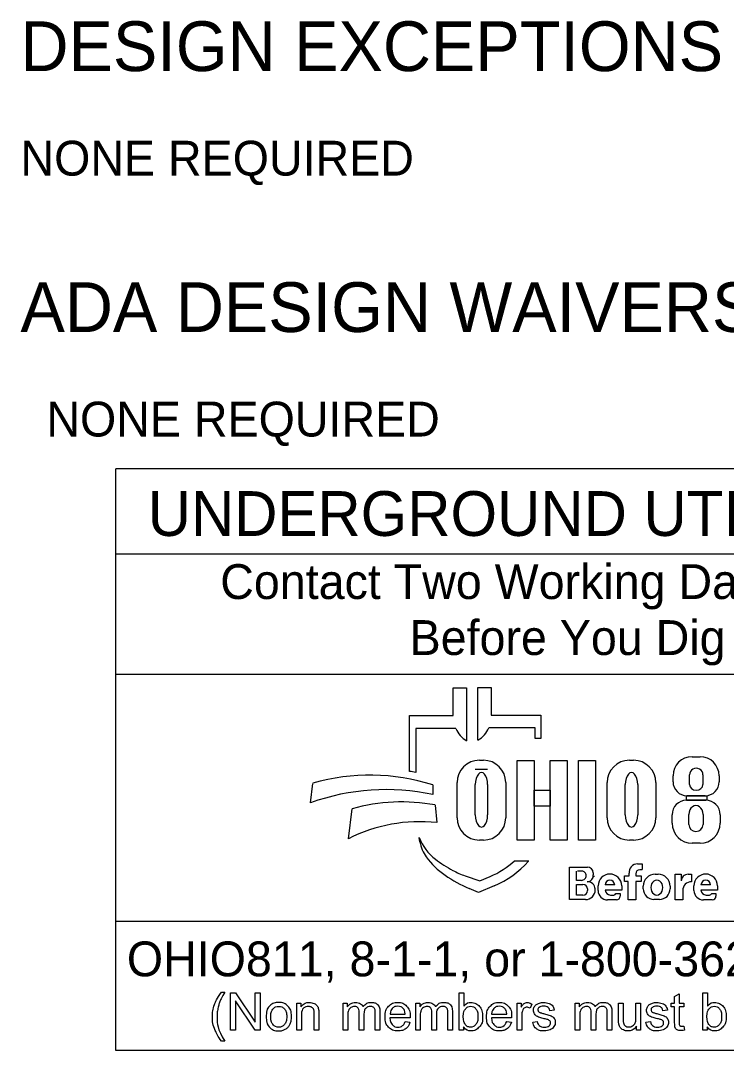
# Model space of a CAD drawing. Extents: x 0 to 34, y 0 to 22.
# Drawn here: x 1.995 to 4.831, y 2.143 to 6.282 of the extents above; entities that cross this region are included whole.
import ezdxf

# ---------------------------------------------------------------- set-up
doc = ezdxf.new("R2010")
doc.units = 0
doc.layers.add('SH_Data', color=7, linetype='Continuous')
doc.layers.add('SH_Text', color=7, linetype='Continuous')

msp = doc.modelspace()

# ---------------------------------------------------------------- linework, layer by layer
at = {"layer": 'SH_Data'}
for p, q in [((2.3775, 2.1428), (2.3775, 4.4803)), ((6.6275, 4.4803), (2.3775, 4.4803)), ((2.3775, 4.1387), (6.6275, 4.1387)), ((2.3775, 3.6553), (6.6275, 3.6553)), ((6.6275, 2.6607), (2.3775, 2.6607)), ((6.6275, 2.1428), (2.3775, 2.1428))]:
    msp.add_line(p, q, dxfattribs=at)
at = {"layer": 'SH_Text'}
for p, q in [((3.8329, 3.39), (3.8329, 3.6021)), ((3.8329, 3.6021), (3.8865, 3.6021)), ((3.8865, 3.6021), (3.8865, 3.4906)), ((3.7335, 3.4883), (3.7335, 3.5998)), ((3.7335, 3.5998), (3.7872, 3.5998)), ((3.7872, 3.5998), (3.7872, 3.3877)), ((3.5576, 3.2644), (3.5576, 3.4883)), ((3.5576, 3.4883), (3.7335, 3.4883)), ((3.8865, 3.4906), (4.0857, 3.4906)), ((4.0857, 3.4906), (4.0857, 3.3968)), ((3.5828, 3.4369), (3.5828, 3.26)), ((3.7439, 3.4369), (3.5828, 3.4369)), ((4.0625, 3.4392), (3.8761, 3.4392)), ((4.0625, 3.3968), (4.0625, 3.4392)), ((4.0857, 3.3968), (4.0625, 3.3968)), ((4.6931, 3.3231), (4.7258, 3.3231)), ((3.8718, 3.2721), (3.822, 3.2721)), ((3.8385, 3.3091), (3.8551, 3.3091)), ((4.4416, 3.3091), (4.4581, 3.3091)), ((4.6168, 3.2225), (4.6168, 3.2468)), ((4.683, 3.2111), (4.683, 3.2504)), ((4.7371, 3.2504), (4.7371, 3.2111)), ((4.8022, 3.2468), (4.8022, 3.2225)), ((3.1602, 3.1381), (3.1696, 3.2162)), ((3.6509, 3.2097), (3.6509, 3.1709)), ((3.7491, 3.0776), (3.7491, 3.2196)), ((3.822, 3.089), (3.822, 3.2114)), ((3.8718, 3.2114), (3.8718, 3.089)), ((3.9445, 3.2196), (3.9445, 3.0776)), ((4.3521, 3.0776), (4.3521, 3.2196)), ((4.425, 3.089), (4.425, 3.2114)), ((4.4748, 3.2114), (4.4748, 3.089)), ((4.5476, 3.2196), (4.5476, 3.0776)), ((4.671, 3.1482), (4.7483, 3.1482)), ((4.7462, 3.1665), (4.6728, 3.1665)), ((3.312, 2.9936), (3.3267, 3.1137)), ((3.6608, 3.1291), (3.6671, 3.0582)), ((4.6131, 3.0563), (4.6131, 3.0903)), ((4.6806, 3.0503), (4.6806, 3.0912)), ((4.7374, 3.0912), (4.7374, 3.0503)), ((4.8062, 3.0903), (4.8062, 3.0563)), ((3.5997, 2.9807), (3.5967, 2.9986)), ((3.8551, 2.9882), (3.8385, 2.9882)), ((4.4581, 2.9882), (4.4416, 2.9882)), ((4.7252, 2.9753), (4.6941, 2.9753)), ((3.98, 2.9048), (4.0375, 2.9048)), ((4.2013, 2.749), (4.2013, 2.8798)), ((4.2013, 2.8798), (4.2725, 2.8798)), ((4.2293, 2.8263), (4.2293, 2.8632)), ((4.2545, 2.8632), (4.2332, 2.8632)), ((4.4739, 2.8926), (4.4934, 2.8926)), ((4.4934, 2.8691), (4.4832, 2.8691)), ((4.4934, 2.8926), (4.4934, 2.8696)), ((3.7816, 2.8444), (3.841, 2.8239)), ((3.841, 2.8239), (3.8821, 2.8417)), ((4.2487, 2.8263), (4.2293, 2.8263)), ((4.2963, 2.856), (4.2963, 2.8481)), ((4.4213, 2.8212), (4.4213, 2.8442)), ((4.4213, 2.8442), (4.4406, 2.8442)), ((4.4362, 2.8212), (4.4213, 2.8212)), ((4.4362, 2.7478), (4.4362, 2.8212)), ((4.4406, 2.8442), (4.4406, 2.8546)), ((4.4667, 2.8526), (4.4667, 2.8442)), ((4.4667, 2.8442), (4.4883, 2.8442)), ((4.4883, 2.8212), (4.4667, 2.8212)), ((4.4667, 2.8212), (4.4667, 2.7478)), ((4.4883, 2.8442), (4.4883, 2.8212)), ((4.5451, 2.8508), (4.5573, 2.8508)), ((4.6254, 2.7478), (4.6254, 2.8505)), ((4.6254, 2.8505), (4.6499, 2.8505)), ((4.6499, 2.8505), (4.6499, 2.8237)), ((4.6772, 2.8505), (4.691, 2.8505)), ((4.691, 2.8505), (4.691, 2.8209)), ((3.835, 2.7769), (3.7976, 2.7934)), ((3.8983, 2.8044), (3.835, 2.7769)), ((4.2293, 2.7669), (4.2293, 2.8097)), ((4.2293, 2.8097), (4.2548, 2.8097)), ((4.2729, 2.7916), (4.2729, 2.7853)), ((4.3043, 2.7887), (4.3043, 2.7884)), ((4.3159, 2.7858), (4.3159, 2.8042)), ((4.3824, 2.8082), (4.3439, 2.8082)), ((4.4104, 2.7866), (4.344, 2.7866)), ((4.4104, 2.8042), (4.4104, 2.7866)), ((4.4973, 2.7922), (4.4973, 2.8029)), ((4.6051, 2.8029), (4.6051, 2.7922)), ((4.6559, 2.786), (4.6559, 2.7478)), ((4.7008, 2.7858), (4.7008, 2.8042)), ((4.7674, 2.8082), (4.7288, 2.8082)), ((4.7953, 2.7866), (4.7289, 2.7866)), ((4.7953, 2.8042), (4.7953, 2.7866)), ((4.265, 2.749), (4.2013, 2.749)), ((4.2546, 2.7669), (4.2293, 2.7669)), ((4.3892, 2.7478), (4.3538, 2.7478)), ((4.3649, 2.7673), (4.379, 2.7673)), ((4.3876, 2.7729), (4.4045, 2.7729)), ((4.4045, 2.7729), (4.4045, 2.7631)), ((4.4667, 2.7478), (4.4362, 2.7478)), ((4.5623, 2.7494), (4.5401, 2.7494)), ((4.6559, 2.7478), (4.6254, 2.7478)), ((4.7742, 2.7478), (4.7388, 2.7478)), ((4.7498, 2.7673), (4.7639, 2.7673)), ((4.7725, 2.7729), (4.7894, 2.7729)), ((4.7894, 2.7729), (4.7894, 2.7631))]:
    msp.add_line(p, q, dxfattribs=at)
for points in [[(3.991, 3.3081), (4.0589, 3.3081), (4.0589, 2.9881), (3.991, 2.9881)], [(4.1231, 3.3081), (4.1911, 3.3081), (4.1911, 2.9881), (4.1231, 2.9881)], [(4.2364, 3.3081), (4.3052, 3.3081), (4.3052, 2.9881), (4.2364, 2.9881)], [(4.0589, 3.1882), (4.1231, 3.1882), (4.1231, 3.1242), (4.0589, 3.1242)], [(4.6706, 3.1665), (4.7523, 3.1665), (4.7523, 3.1481), (4.6706, 3.1481)]]:
    msp.add_lwpolyline(points, close=True, dxfattribs=at)
for points in [[(2.8021, 2.3766), (2.8153, 2.3766)], [(2.8389, 2.2239), (2.8389, 2.3741), (2.8592, 2.3741), (2.9382, 2.2561), (2.9382, 2.3741), (2.9572, 2.3741), (2.9572, 2.2239), (2.9369, 2.2239), (2.8579, 2.3419), (2.8579, 2.2239), (2.8389, 2.2239)], [(3.7743, 2.2239), (3.7573, 2.2239), (3.7573, 2.3741), (3.7757, 2.3741), (3.7757, 2.3206)], [(4.6233, 2.2558), (4.6233, 2.3185), (4.6097, 2.3185), (4.6097, 2.3328), (4.6233, 2.3328), (4.6233, 2.3597), (4.6417, 2.3708), (4.6417, 2.3328), (4.6601, 2.3328), (4.6601, 2.3185), (4.6417, 2.3185), (4.6417, 2.2547)], [(4.7534, 2.2239), (4.7363, 2.2239), (4.7363, 2.3741), (4.7548, 2.3741), (4.7548, 2.3206)], [(3.1048, 2.2239), (3.1048, 2.3328), (3.1214, 2.3328), (3.1214, 2.3173)], [(3.2912, 2.2239), (3.2912, 2.3328), (3.3077, 2.3328), (3.3077, 2.3174)], [(3.5826, 2.2239), (3.5826, 2.3328), (3.5991, 2.3328), (3.5991, 2.3174)], [(3.9904, 2.2239), (3.9904, 2.3328), (4.007, 2.3328), (4.007, 2.3163)], [(4.0495, 2.3293), (4.043, 2.3122)], [(4.2236, 2.2239), (4.2236, 2.3328), (4.2401, 2.3328), (4.2401, 2.3174)], [(4.3979, 2.2654), (4.3979, 2.3328), (4.4164, 2.3328), (4.4164, 2.2724)], [(4.4676, 2.2745), (4.4676, 2.3328), (4.4861, 2.3328), (4.4861, 2.2239), (4.4696, 2.2239)], [(3.1233, 2.2833), (3.1233, 2.2239), (3.1048, 2.2239)], [(3.1932, 2.2908), (3.1932, 2.2239), (3.1748, 2.2239), (3.1748, 2.2901)], [(3.3097, 2.2803), (3.3097, 2.2239), (3.2912, 2.2239)], [(3.3743, 2.2871), (3.3743, 2.2239), (3.3559, 2.2239), (3.3559, 2.2946)], [(3.4388, 2.2986), (3.4388, 2.2239), (3.4203, 2.2239), (3.4203, 2.2924)], [(3.4799, 2.2887), (3.5406, 2.2887)], [(3.601, 2.2803), (3.601, 2.2239), (3.5826, 2.2239)], [(3.6657, 2.2871), (3.6657, 2.2239), (3.6473, 2.2239), (3.6473, 2.2946)], [(3.7301, 2.2986), (3.7301, 2.2239), (3.7117, 2.2239), (3.7117, 2.2924)], [(3.8879, 2.2887), (3.9486, 2.2887)], [(4.0088, 2.2809), (4.0088, 2.2239), (3.9904, 2.2239)], [(4.1394, 2.3046), (4.1213, 2.3022)], [(4.242, 2.2803), (4.242, 2.2239), (4.2236, 2.2239)], [(4.3067, 2.2871), (4.3067, 2.2239), (4.2883, 2.2239), (4.2883, 2.2946)], [(4.3711, 2.2986), (4.3711, 2.2239), (4.3527, 2.2239), (4.3527, 2.2924)], [(4.594, 2.3046), (4.5759, 2.3022)], [(3.56, 2.2736), (3.4788, 2.2736)], [(3.5404, 2.2591), (3.5595, 2.2567)], [(3.7743, 2.2375), (3.7743, 2.2239)], [(3.968, 2.2736), (3.8868, 2.2736)], [(3.9484, 2.2591), (3.9675, 2.2567)], [(4.053, 2.2564), (4.0712, 2.2593)], [(4.4696, 2.2239), (4.4696, 2.24)], [(4.5076, 2.2564), (4.5258, 2.2593)], [(4.6601, 2.2404), (4.6628, 2.2241)], [(4.7534, 2.2375), (4.7534, 2.2239)], [(2.8153, 2.1798), (2.8021, 2.1798)]]:
    msp.add_lwpolyline(points, dxfattribs=at)
for centre, radius, start, end in [((3.8353, 3.4736), 0.0985, 201.9296, 240.7469), ((3.7847, 3.476), 0.0985, 299.2531, 338.0704), ((4.6931, 3.2468), 0.0763, 90, 180), ((4.7258, 3.2468), 0.0763, 0, 90), ((3.8385, 3.2196), 0.0895, 90, 180), ((3.8551, 3.2196), 0.0895, 0, 90), ((4.4416, 3.2196), 0.0895, 90, 180), ((4.4581, 3.2196), 0.0895, 0, 90), ((3.3997, 2.4302), 0.8191, 72.1402, 106.3144), ((3.4295, 2.4554), 0.8191, 79.2074, 81.0007), ((3.4628, 2.2991), 0.8919, 77.8238, 109.8274), ((4.6728, 3.2225), 0.056, 180, 270), ((4.7462, 3.2225), 0.056, 270, 0), ((4.671, 3.0903), 0.0579, 90, 180), ((4.7483, 3.0903), 0.0579, 0, 90), ((3.5267, 2.4094), 0.7322, 79.44, 105.8467), ((3.8385, 3.0776), 0.0895, 180, 270), ((3.8551, 3.0776), 0.0895, 270, 0), ((4.4416, 3.0776), 0.0895, 180, 270), ((4.4581, 3.0776), 0.0895, 270, 0), ((3.5987, 2.4262), 0.6357, 83.8248, 116.8021), ((4.6941, 3.0563), 0.081, 180, 270), ((4.7252, 3.0563), 0.081, 270, 0), ((3.7841, 3.0707), 0.2008, 201.0457, 232.5314), ((3.741, 3.0048), 0.1433, 189.6817, 216.0884), ((3.8747, 3.1022), 0.3088, 216.0884, 235.7167), ((3.9766, 3.3219), 0.5173, 232.5314, 241.794), ((3.7387, 3.1722), 0.3602, 293.4582, 312.0712), ((3.7387, 3.1722), 0.401, 293.4582, 317.8286), ((3.8914, 3.1631), 0.3371, 241.794, 250.9821), ((4.2505, 2.8463), 0.0169, 357.8325, 90), ((4.2725, 2.856), 0.0238, 0, 90), ((4.4739, 2.859), 0.0335, 90, 187.5187), ((4.4832, 2.8526), 0.0165, 90, 180), ((4.0412, 3.3465), 0.6044, 235.7167, 246.2325), ((4.2487, 2.845), 0.0187, 270, 2.0582), ((4.2721, 2.8453), 0.0243, 270, 6.6529), ((4.2722, 2.7889), 0.0321, 4.0748, 90), ((4.2827, 2.8438), 0.0175, 347.4023, 0), ((4.3631, 2.8042), 0.0473, 0, 180), ((4.3632, 2.8072), 0.0193, 2.9632, 177.0368), ((4.5451, 2.8029), 0.0478, 90, 180), ((4.5573, 2.8029), 0.0478, 0, 90), ((4.6768, 2.8237), 0.0269, 89.2449, 180), ((4.6908, 2.786), 0.0349, 89.6033, 180), ((4.7481, 2.8042), 0.0473, 0, 180), ((4.7481, 2.8072), 0.0193, 2.9632, 177.0368), ((4.2546, 2.7853), 0.0184, 270, 0), ((4.2548, 2.7916), 0.0181, 0, 90), ((4.265, 2.7884), 0.0393, 270, 0), ((4.2714, 2.7887), 0.033, 0, 11.7502), ((4.3538, 2.7858), 0.038, 180, 270), ((4.3649, 2.7883), 0.021, 184.827, 270), ((4.5401, 2.7922), 0.0428, 180, 270), ((4.5623, 2.7922), 0.0428, 270, 0), ((4.7388, 2.7858), 0.038, 180, 270), ((4.7498, 2.7883), 0.021, 184.827, 270), ((4.379, 2.7767), 0.00938, 270, 335.9979), ((4.3892, 2.7631), 0.0152, 270, 0), ((4.7639, 2.7767), 0.00938, 270, 335.9979), ((4.7742, 2.7631), 0.0152, 270, 0)]:
    msp.add_arc(centre, radius, start, end, dxfattribs=at)
for centre, major_axis, ratio, start_param, end_param in [((4.71, 3.2504), (0.0271, 0), 0.969373, 0, 3.141593), ((3.8469, 3.2114), (0, 0.0484), 0.514403, 4.712389, 7.853982), ((4.4499, 3.2114), (0, 0.0484), 0.514403, 4.712389, 7.853982), ((4.71, 3.2111), (0.0271, 0), 0.818453, 3.141593, 6.283185), ((4.709, 3.0912), (0, 0.0358), 0.794529, 4.712389, 7.853982), ((3.8469, 3.089), (0, 0.0484), 0.514403, 1.570796, 4.712389), ((4.4499, 3.089), (0, 0.0484), 0.514403, 1.570796, 4.712389), ((4.709, 3.0503), (0.0284, 0), 0.959837, 3.141593, 6.283185), ((4.5517, 2.7976), (0, 0.029), 0.832186, 4.712389, 7.853982), ((4.5517, 2.7976), (0, 0.0302), 0.797287, 1.570796, 4.712389)]:
    msp.add_ellipse(centre, major_axis=major_axis, ratio=ratio, start_param=start_param, end_param=end_param, dxfattribs=at)
for points in [[(2.8021, 2.1798), (2.7869, 2.199), (2.7763, 2.2248), (2.7657, 2.2506), (2.7657, 2.2783), (2.7657, 2.3026), (2.7736, 2.325), (2.7829, 2.3509), (2.8021, 2.3766)], [(2.8153, 2.3766), (2.8029, 2.3553), (2.7989, 2.3462), (2.7927, 2.332), (2.7891, 2.3167), (2.7847, 2.2975), (2.7847, 2.2782), (2.7847, 2.2289), (2.8153, 2.1798)], [(2.9814, 2.2783), (2.9814, 2.3085), (2.9981, 2.3231), (3.0122, 2.3352), (3.0323, 2.3352), (3.0547, 2.3352), (3.069, 2.3205), (3.0832, 2.3058), (3.0832, 2.2799), (3.0832, 2.2589), (3.0769, 2.2469), (3.0706, 2.2348), (3.0586, 2.2282), (3.0466, 2.2215), (3.0323, 2.2215), (3.0095, 2.2215), (2.9954, 2.2362), (2.9814, 2.2508), (2.9814, 2.2783)], [(3.0003, 2.2783), (3.0003, 2.2574), (3.0094, 2.247), (3.0185, 2.2366), (3.0323, 2.2366), (3.046, 2.2366), (3.0551, 2.2471), (3.0642, 2.2575), (3.0642, 2.279), (3.0642, 2.2991), (3.0551, 2.3095), (3.0459, 2.3199), (3.0323, 2.3199), (3.0185, 2.3199), (3.0094, 2.3096), (3.0003, 2.2992), (3.0003, 2.2783)], [(3.1214, 2.3173), (3.1334, 2.3352), (3.156, 2.3352), (3.1659, 2.3352), (3.1741, 2.3316), (3.1823, 2.3281), (3.1864, 2.3224), (3.1905, 2.3166), (3.1922, 2.3087), (3.1932, 2.3036), (3.1932, 2.2908)], [(3.1748, 2.2901), (3.1748, 2.3013), (3.1726, 2.3069), (3.1705, 2.3125), (3.165, 2.3158), (3.1595, 2.3191), (3.1521, 2.3191), (3.1404, 2.3191), (3.1318, 2.3117), (3.1233, 2.3042), (3.1233, 2.2833)], [(3.3077, 2.3174), (3.3128, 2.3254), (3.3214, 2.3303), (3.3299, 2.3352), (3.3407, 2.3352), (3.3528, 2.3352), (3.3606, 2.3301), (3.3683, 2.3251), (3.3715, 2.3161), (3.3844, 2.3352), (3.4051, 2.3352), (3.4213, 2.3352), (3.43, 2.3262), (3.4388, 2.3172), (3.4388, 2.2986)], [(3.3559, 2.2946), (3.3559, 2.3069), (3.3514, 2.313), (3.3469, 2.3191), (3.3366, 2.3191), (3.3288, 2.3191), (3.3222, 2.315), (3.3156, 2.311), (3.3126, 2.3031), (3.3097, 2.2952), (3.3097, 2.2803)], [(3.4203, 2.2924), (3.4203, 2.3035), (3.4185, 2.3083), (3.4168, 2.3132), (3.412, 2.3162), (3.4073, 2.3191), (3.401, 2.3191), (3.3895, 2.3191), (3.3819, 2.3115), (3.3743, 2.3039), (3.3743, 2.2871)], [(3.5595, 2.2567), (3.555, 2.24), (3.5428, 2.2307), (3.5306, 2.2215), (3.5117, 2.2215), (3.4878, 2.2215), (3.4738, 2.2362), (3.4598, 2.2509), (3.4598, 2.2774), (3.4598, 2.3049), (3.474, 2.32), (3.4881, 2.3352), (3.5106, 2.3352), (3.5324, 2.3352), (3.5463, 2.3203), (3.5601, 2.3055), (3.5601, 2.2785), (3.5601, 2.2769), (3.56, 2.2736)], [(3.5406, 2.2887), (3.5394, 2.3025), (3.5337, 2.3094), (3.5249, 2.3201), (3.5108, 2.3201), (3.4981, 2.3201), (3.4894, 2.3115), (3.4808, 2.303), (3.4799, 2.2887)], [(3.5991, 2.3174), (3.6042, 2.3254), (3.6127, 2.3303), (3.6212, 2.3352), (3.6321, 2.3352), (3.6442, 2.3352), (3.6519, 2.3301), (3.6597, 2.3251), (3.6628, 2.3161), (3.6758, 2.3352), (3.6965, 2.3352), (3.7127, 2.3352), (3.7214, 2.3262), (3.7301, 2.3172), (3.7301, 2.2986)], [(3.6473, 2.2946), (3.6473, 2.3069), (3.6428, 2.313), (3.6383, 2.3191), (3.628, 2.3191), (3.6202, 2.3191), (3.6136, 2.315), (3.607, 2.311), (3.604, 2.3031), (3.601, 2.2952), (3.601, 2.2803)], [(3.7117, 2.2924), (3.7117, 2.3035), (3.7099, 2.3083), (3.7081, 2.3132), (3.7034, 2.3162), (3.6987, 2.3191), (3.6923, 2.3191), (3.6809, 2.3191), (3.6733, 2.3115), (3.6657, 2.3039), (3.6657, 2.2871)], [(3.7741, 2.2792), (3.7741, 2.2596), (3.7794, 2.2509), (3.7881, 2.2366), (3.8029, 2.2366), (3.815, 2.2366), (3.8238, 2.2471), (3.8326, 2.2576), (3.8326, 2.2784), (3.8326, 2.2998), (3.8241, 2.3099), (3.8157, 2.3201), (3.8038, 2.3201), (3.7917, 2.3201), (3.7829, 2.3096), (3.7741, 2.299), (3.7741, 2.2792)], [(3.7757, 2.3206), (3.7874, 2.3352), (3.8055, 2.3352), (3.8155, 2.3352), (3.8245, 2.3311), (3.8335, 2.3271), (3.8392, 2.3198), (3.845, 2.3124), (3.8483, 2.3021), (3.8516, 2.2918), (3.8516, 2.28), (3.8516, 2.252), (3.8378, 2.2368), (3.8239, 2.2215), (3.8046, 2.2215), (3.7853, 2.2215), (3.7743, 2.2375)], [(3.9675, 2.2567), (3.963, 2.24), (3.9508, 2.2307), (3.9386, 2.2215), (3.9196, 2.2215), (3.8958, 2.2215), (3.8818, 2.2362), (3.8678, 2.2509), (3.8678, 2.2774), (3.8678, 2.3049), (3.882, 2.32), (3.8961, 2.3352), (3.9186, 2.3352), (3.9404, 2.3352), (3.9543, 2.3203), (3.9681, 2.3055), (3.9681, 2.2785), (3.9681, 2.2769), (3.968, 2.2736)], [(3.9486, 2.2887), (3.9474, 2.3025), (3.9417, 2.3094), (3.9328, 2.3201), (3.9188, 2.3201), (3.9061, 2.3201), (3.8974, 2.3115), (3.8888, 2.303), (3.8879, 2.2887)], [(4.007, 2.3163), (4.0133, 2.3278), (4.0187, 2.3315), (4.0241, 2.3352), (4.0305, 2.3352), (4.0398, 2.3352), (4.0495, 2.3293)], [(4.1213, 2.3022), (4.1201, 2.3106), (4.1142, 2.3153), (4.1083, 2.3201), (4.0975, 2.3201), (4.0848, 2.3201), (4.0794, 2.3159), (4.0739, 2.3116), (4.0739, 2.306), (4.0739, 2.3024), (4.0762, 2.2995), (4.0785, 2.2966), (4.0833, 2.2946), (4.086, 2.2936), (4.0996, 2.2899), (4.1192, 2.2847), (4.1269, 2.2813), (4.1347, 2.278), (4.1391, 2.2717), (4.1435, 2.2653), (4.1435, 2.2559), (4.1435, 2.2467), (4.1381, 2.2386), (4.1327, 2.2304), (4.1226, 2.226), (4.1124, 2.2215), (4.0996, 2.2215), (4.0784, 2.2215), (4.0672, 2.2303), (4.0561, 2.2391), (4.053, 2.2564)], [(4.0712, 2.2593), (4.0727, 2.2483), (4.0798, 2.2425), (4.0868, 2.2366), (4.0995, 2.2366), (4.1122, 2.2366), (4.1184, 2.2418), (4.1245, 2.247), (4.1245, 2.254), (4.1245, 2.2602), (4.1191, 2.2638), (4.1153, 2.2663), (4.1002, 2.2701), (4.0799, 2.2752), (4.072, 2.2789), (4.0642, 2.2827), (4.0601, 2.2893), (4.0561, 2.2959), (4.0561, 2.3038), (4.0561, 2.3111), (4.0594, 2.3173), (4.0628, 2.3235), (4.0685, 2.3276), (4.0728, 2.3308), (4.0803, 2.333), (4.0877, 2.3352), (4.0962, 2.3352), (4.109, 2.3352), (4.1187, 2.3315), (4.1284, 2.3278), (4.133, 2.3215), (4.1377, 2.3152), (4.1394, 2.3046)], [(4.2401, 2.3174), (4.2452, 2.3254), (4.2537, 2.3303), (4.2622, 2.3352), (4.2731, 2.3352), (4.2852, 2.3352), (4.2929, 2.3301), (4.3007, 2.3251), (4.3038, 2.3161), (4.3168, 2.3352), (4.3375, 2.3352), (4.3537, 2.3352), (4.3624, 2.3262), (4.3711, 2.3172), (4.3711, 2.2986)], [(4.2883, 2.2946), (4.2883, 2.3069), (4.2838, 2.313), (4.2793, 2.3191), (4.269, 2.3191), (4.2612, 2.3191), (4.2546, 2.315), (4.248, 2.311), (4.245, 2.3031), (4.242, 2.2952), (4.242, 2.2803)], [(4.3527, 2.2924), (4.3527, 2.3035), (4.3509, 2.3083), (4.3491, 2.3132), (4.3444, 2.3162), (4.3397, 2.3191), (4.3333, 2.3191), (4.3219, 2.3191), (4.3143, 2.3115), (4.3067, 2.3039), (4.3067, 2.2871)], [(4.5759, 2.3022), (4.5747, 2.3106), (4.5688, 2.3153), (4.5629, 2.3201), (4.5521, 2.3201), (4.5394, 2.3201), (4.5339, 2.3159), (4.5285, 2.3116), (4.5285, 2.306), (4.5285, 2.3024), (4.5308, 2.2995), (4.533, 2.2966), (4.5378, 2.2946), (4.5406, 2.2936), (4.5542, 2.2899), (4.5737, 2.2847), (4.5815, 2.2813), (4.5893, 2.278), (4.5937, 2.2717), (4.5981, 2.2653), (4.5981, 2.2559), (4.5981, 2.2467), (4.5927, 2.2386), (4.5873, 2.2304), (4.5772, 2.226), (4.567, 2.2215), (4.5542, 2.2215), (4.5329, 2.2215), (4.5218, 2.2303), (4.5107, 2.2391), (4.5076, 2.2564)], [(4.5258, 2.2593), (4.5273, 2.2483), (4.5343, 2.2425), (4.5414, 2.2366), (4.554, 2.2366), (4.5668, 2.2366), (4.5729, 2.2418), (4.5791, 2.247), (4.5791, 2.254), (4.5791, 2.2602), (4.5736, 2.2638), (4.5698, 2.2663), (4.5548, 2.2701), (4.5345, 2.2752), (4.5266, 2.2789), (4.5188, 2.2827), (4.5147, 2.2893), (4.5107, 2.2959), (4.5107, 2.3038), (4.5107, 2.3111), (4.514, 2.3173), (4.5173, 2.3235), (4.5231, 2.3276), (4.5274, 2.3308), (4.5348, 2.333), (4.5423, 2.3352), (4.5508, 2.3352), (4.5636, 2.3352), (4.5733, 2.3315), (4.583, 2.3278), (4.5876, 2.3215), (4.5922, 2.3152), (4.594, 2.3046)], [(4.7532, 2.2792), (4.7532, 2.2596), (4.7585, 2.2509), (4.7672, 2.2366), (4.782, 2.2366), (4.7941, 2.2366), (4.8029, 2.2471), (4.8116, 2.2576), (4.8116, 2.2784), (4.8116, 2.2998), (4.8032, 2.3099), (4.7948, 2.3201), (4.7828, 2.3201), (4.7708, 2.3201), (4.762, 2.3096), (4.7532, 2.299), (4.7532, 2.2792)], [(4.7548, 2.3206), (4.7664, 2.3352), (4.7846, 2.3352), (4.7946, 2.3352), (4.8036, 2.3311), (4.8125, 2.3271), (4.8183, 2.3198), (4.8241, 2.3124), (4.8274, 2.3021), (4.8306, 2.2918), (4.8306, 2.28), (4.8306, 2.252), (4.8168, 2.2368), (4.803, 2.2215), (4.7836, 2.2215), (4.7644, 2.2215), (4.7534, 2.2375)], [(4.043, 2.3122), (4.0363, 2.3162), (4.0295, 2.3162), (4.0235, 2.3162), (4.0187, 2.3125), (4.0139, 2.3089), (4.0119, 2.3024), (4.0088, 2.2926), (4.0088, 2.2809)], [(3.4788, 2.2736), (3.4799, 2.2557), (3.489, 2.2462), (3.4981, 2.2366), (3.5117, 2.2366), (3.5219, 2.2366), (3.5291, 2.242), (3.5362, 2.2473), (3.5404, 2.2591)], [(3.8868, 2.2736), (3.8879, 2.2557), (3.897, 2.2462), (3.9061, 2.2366), (3.9197, 2.2366), (3.9299, 2.2366), (3.937, 2.242), (3.9442, 2.2473), (3.9484, 2.2591)], [(4.4696, 2.24), (4.4569, 2.2215), (4.4351, 2.2215), (4.4255, 2.2215), (4.4171, 2.2252), (4.4088, 2.2289), (4.4047, 2.2345), (4.4007, 2.2401), (4.3991, 2.2482), (4.3979, 2.2536), (4.3979, 2.2654)], [(4.4164, 2.2724), (4.4164, 2.258), (4.4175, 2.253), (4.4192, 2.2457), (4.4249, 2.2416), (4.4305, 2.2374), (4.4388, 2.2374), (4.4471, 2.2374), (4.4543, 2.2417), (4.4616, 2.2459), (4.4646, 2.2533), (4.4676, 2.2606), (4.4676, 2.2745)], [(4.6628, 2.2241), (4.655, 2.2224), (4.6488, 2.2224), (4.6388, 2.2224), (4.6333, 2.2256), (4.6278, 2.2288), (4.6255, 2.234), (4.6233, 2.2392), (4.6233, 2.2558)], [(4.6417, 2.2547), (4.6417, 2.2468), (4.6427, 2.2445), (4.6436, 2.2423), (4.6458, 2.2409), (4.648, 2.2396), (4.6521, 2.2396), (4.6551, 2.2396), (4.6601, 2.2404)]]:
    msp.add_open_spline(points, degree=3, dxfattribs=at)

# ---------------------------------------------------------------- texts
for s, height, p in [('DESIGN EXCEPTIONS', 0.2, (1.9944, 6.079)), ('NONE REQUIRED', 0.14, (1.9944, 5.659)), ('ADA DESIGN WAIVERS', 0.2, (1.9944, 5.0303)), ('  NONE REQUIRED', 0.14, (1.9944, 4.6103)), ('UNDERGROUND UTILITIES', 0.18, (2.5057, 4.2106)), ('Contact Two Working Days', 0.14, (2.7972, 3.9571)), ('Before You Dig', 0.14, (3.5583, 3.7321)), ('OHIO811, 8-1-1, or 1-800-362-2764', 0.14, (2.422, 2.4406))]:
    msp.add_text(s, height=height, dxfattribs=at).set_placement(p)

doc.saveas('drawing.dxf')
